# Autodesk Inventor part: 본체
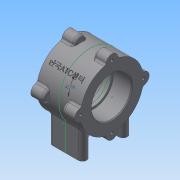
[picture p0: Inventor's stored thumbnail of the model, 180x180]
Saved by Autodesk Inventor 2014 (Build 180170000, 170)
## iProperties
Created: 2015-03
Part Number: 본체
Material: 일반
Document SubType Name: Modeling
Designer: net
Density: 1 g/cm^3
Appearance: 기본값
Author: net
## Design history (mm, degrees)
sketch "스케치1"
  geometry: 1 further point
sketch "스케치2"
  geometry: C1 r 37 at (0, 0); 1 further point
  constraints: 1 centre point, 1 coincident
  dimensions: "d0" = 74 diameter of C1
extrude "돌출1" new body sketch "스케치2" distance "d1" = 52; taper "d2" = 0 deg
sketch "스케치3"
  geometry: A1 r 37 centre (0, 0) between (0, 37) and (-6.969, 36.338) reference; A2 r 7 centre (0, 37) between (6.969, 36.338) and (-6.969, 36.338)
  constraints: 5 point on circle, 1 centre point, 1 vertical alignment
  dimensions: "d3" = 14 diameter of A2
extrude "돌출2" join sketch "스케치3" distance "d4" = 15; taper "d5" = 0 deg
node "작업 평면1"
hole "구멍1" diameter "d15" = 47; stored, may be unused: countersink angle "d19" = 90 deg, drill point angle "d21" = 0 deg; dims "d13" = 10, "d14" = 10, "d16" = 6, "d17" = 4, "d18" = 2, "d20" = 22
hole "구멍2" diameter "d24" = 47; stored, may be unused: countersink angle "d28" = 90 deg, drill point angle "d30" = 0 deg; dims "d22" = 10, "d23" = 10, "d25" = 6, "d26" = 4, "d27" = 2, "d29" = 22
hole "구멍3" diameter "d33" = 42; stored, may be unused: countersink angle "d37" = 90 deg, drill point angle "d39" = 0 deg; dims "d31" = 10, "d32" = 10, "d34" = 6, "d35" = 4, "d36" = 2, "d38" = 22
hole "구멍4" diameter "d42" = 3.459; stored, may be unused: countersink angle "d46" = 90 deg, drill point angle "d48" = 118 deg; dims "d40" = 10, "d41" = 10, "d43" = 8, "d44" = 4, "d45" = 2, "d47" = 11
node "작업 평면3"
sketch "스케치5"
  geometry: L1 (29, -11)-(29, -41); L2 (19, -11)-(19, -41); L3 (-19, -11)-(-19, -41); L4 (-29, -11)-(-29, -41); L5 (6.969, -52)-(36.338, -52) reference; L6 (6.969, 0)-(36.338, 0) reference; L7 (37, -15)-(37, -37) reference; L8 (-37, -15)-(-37, -37) reference; A1 r 5 centre (24, -11) between (19, -11) and (29, -11); A2 r 5 centre (24, -41) between (29, -41) and (19, -41); A3 r 5 centre (-24, -41) between (-19, -41) and (-29, -41); A4 r 5 centre (-24, -11) between (-29, -11) and (-19, -11); 1 further point
  constraints: 8 end point, 8 point on circle, 4 centre point, 4 tangent, 3 equal radius, 3 parallel, 2 horizontal alignment, 2 vertical alignment, 1 vertical
  dimensions: "d53" = 10 diameter of A1; "d54" = 11 distance from line of L5 A2.centre; "d55" = 11 distance from line of A1.centre L6; "d56" = 48 distance of A3.centre A2.centre; "d57" = 8 distance between parallel lines of L8 L4
extrude "돌출3" join sketch "스케치5" stored distance "d58" = 15; taper "d59" = 0 deg
fillet "모깎기1" dims "d60" = 3
fillet "모깎기2" dims "d64" = 3
fillet "모깎기3" dims "d65" = 0.3
hole "구멍5" diameter "d68" = 4.134; stored, may be unused: countersink angle "d72" = 90 deg, drill point angle "d74" = 118 deg; dims "d66" = 10, "d67" = 10, "d69" = 6, "d70" = 4, "d71" = 2, "d73" = 8
hole "구멍6" diameter "d77" = 4.134; stored, may be unused: countersink angle "d81" = 90 deg, drill point angle "d83" = 118 deg; dims "d75" = 10, "d76" = 10, "d78" = 6, "d79" = 4, "d80" = 2, "d82" = 8
hole "구멍7" diameter "d86" = 4.134; stored, may be unused: countersink angle "d90" = 90 deg, drill point angle "d92" = 118 deg; dims "d84" = 10, "d85" = 10, "d87" = 6, "d88" = 4, "d89" = 2, "d91" = 8
hole "구멍8" diameter "d95" = 4.134; stored, may be unused: countersink angle "d99" = 90 deg, drill point angle "d101" = 118 deg; dims "d93" = 10, "d94" = 10, "d96" = 6, "d97" = 4, "d98" = 2, "d100" = 8
sketch "스케치6"
  geometry: L1 (29, -24)-(29, -56) reference; L2 (29, -56)-(19, -56) reference; L3 (19, -56)-(19, -36.661) reference; L4 (-19, -36.661)-(-19, -56) reference; L5 (-19, -56)-(-29, -56) reference; L6 (-29, -56)-(-29, -24) reference; L7 (0, 0)-(-26.163, 26.163); L8 (0, 0)-(-37, 0); C1 r 21 at (0, 0) reference; A1 r 3 centre (-32, -24) between (-29, -24) and (-29.6, -22.2) reference; A2 r 37 centre (0, 0) between (29.6, -22.2) and (-29.6, -22.2) reference; A3 r 3 centre (32, -24) between (29.6, -22.2) and (29, -24) reference; A4 r 3 centre (16, -36.661) between (19, -36.661) and (14.8, -33.911) reference; A5 r 37 centre (0, 0) between (-14.8, -33.911) and (14.8, -33.911) reference; A6 r 3 centre (-16, -36.661) between (-14.8, -33.911) and (-19, -36.661) reference; 2 further points
  constraints: 4 end point, 2 point on circle, 1 coincident, 1 perpendicular
  dimensions: "d102" = 45 deg angle of L8 L7
  node "절단 모서리 투영1"
node "작업 평면4"
sketch "스케치7"
  geometry: 3 further points
  constraints: 1 coincident, 1 other
feature "엠보싱1" sketch "스케치7" dims "d0" = 74, "d103" = 0.5, "d104" = 0
chamfer "모따기1" distance "d105" = 1; stored, may be unused: second distance "d106" = 2, angle "d107" = 45 deg
node "솔리드1"
pattern_circular "원형 패턴1" dims angle "d7" = 360 deg
mirror "대칭1"
pattern_circular "원형 패턴2" dims angle "d50" = 360 deg
mirror "대칭2"
pattern_circular "원형 패턴3" dims angle "d62" = 360 deg
mirror "대칭3"
other parameters: "d52" = -56
